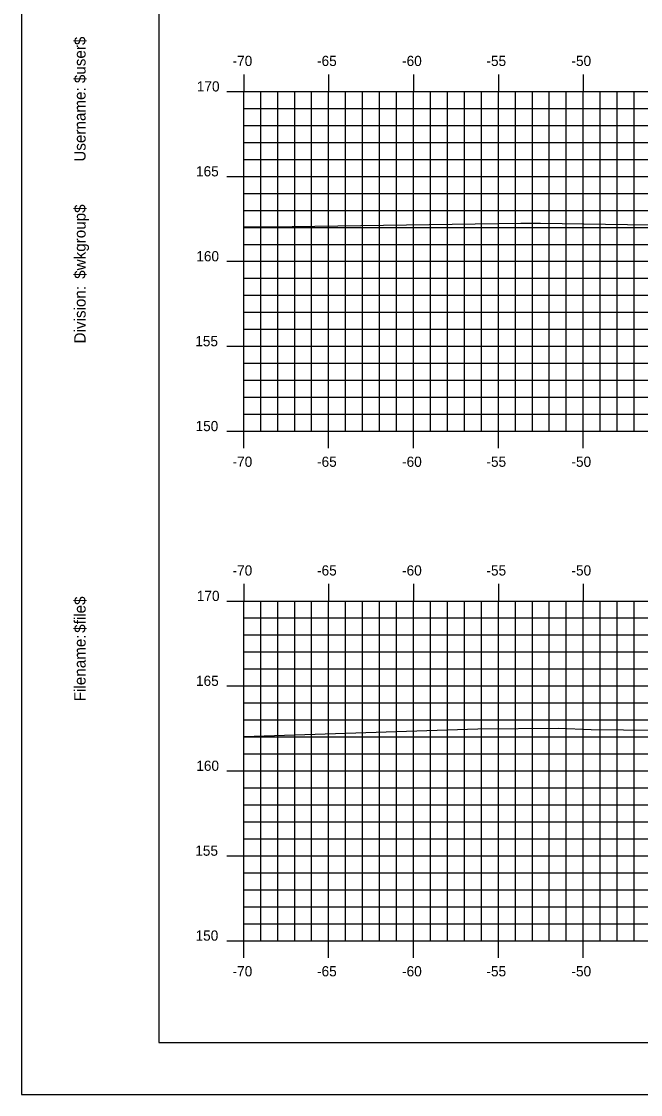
# Model space of a CAD drawing. Extents: x 1143198 to 1143368, y 608981 to 609091.
# Drawn here: x 1143198.2 to 1143234.7, y 608981.3 to 609044.5 of the extents above; entities that cross this region are included whole.
import ezdxf

# ---------------------------------------------------------------- set-up
doc = ezdxf.new("R2010")
doc.units = 0
for name, color, linetype in [('BORDER', 7, 'Continuous'), ('H_V ANNOTATION', 7, 'Continuous'), ('MAJOR', 7, 'Continuous'), ('MINOR', 7, 'Continuous'), ('PLOT BOUNDARY', 7, 'Continuous'), ('S_Roadway_Centerline', 7, 'Continuous')]:
    doc.layers.add(name, color=color, linetype=linetype)

msp = doc.modelspace()

# ---------------------------------------------------------------- linework, layer by layer
at = {"layer": 'BORDER'}
msp.add_lwpolyline([(1143206.323, 608984.335), (1143366.323, 608984.335), (1143366.323, 609089.335), (1143206.323, 609089.335)], close=True, dxfattribs=at)
at = {"layer": 'MAJOR'}
for p, q in [((1143211.323, 609041.337), (1143211.323, 609040.335)), ((1143216.323, 609041.337), (1143216.323, 609040.335)), ((1143221.323, 609041.337), (1143221.323, 609040.335)), ((1143226.323, 609041.337), (1143226.323, 609040.335)), ((1143231.323, 609041.337), (1143231.323, 609040.335)), ((1143210.321, 609040.335), (1143211.323, 609040.335)), ((1143211.323, 609040.335), (1143351.323, 609040.335)), ((1143211.323, 609020.335), (1143211.323, 609040.335)), ((1143211.323, 609020.335), (1143211.323, 609040.335)), ((1143211.323, 609040.335), (1143351.323, 609040.335)), ((1143216.323, 609020.335), (1143216.323, 609040.335)), ((1143221.323, 609020.335), (1143221.323, 609040.335)), ((1143226.323, 609020.335), (1143226.323, 609040.335)), ((1143231.323, 609020.335), (1143231.323, 609040.335)), ((1143210.321, 609035.335), (1143211.323, 609035.335)), ((1143211.323, 609035.335), (1143351.323, 609035.335)), ((1143210.321, 609030.335), (1143211.323, 609030.335)), ((1143211.323, 609030.335), (1143351.323, 609030.335)), ((1143210.321, 609025.335), (1143211.323, 609025.335)), ((1143211.323, 609025.335), (1143351.323, 609025.335)), ((1143210.321, 609020.335), (1143211.323, 609020.335)), ((1143211.323, 609020.335), (1143351.323, 609020.335)), ((1143211.323, 609020.335), (1143351.323, 609020.335)), ((1143211.323, 609019.333), (1143211.323, 609020.335)), ((1143216.323, 609019.333), (1143216.323, 609020.335)), ((1143221.323, 609019.333), (1143221.323, 609020.335)), ((1143226.323, 609019.333), (1143226.323, 609020.335)), ((1143231.323, 609019.333), (1143231.323, 609020.335)), ((1143211.323, 609011.337), (1143211.323, 609010.335)), ((1143216.323, 609011.337), (1143216.323, 609010.335)), ((1143221.323, 609011.337), (1143221.323, 609010.335)), ((1143226.323, 609011.337), (1143226.323, 609010.335)), ((1143231.323, 609011.337), (1143231.323, 609010.335)), ((1143210.321, 609010.335), (1143211.323, 609010.335)), ((1143211.323, 609010.335), (1143351.323, 609010.335)), ((1143211.323, 608990.335), (1143211.323, 609010.335)), ((1143211.323, 608990.335), (1143211.323, 609010.335)), ((1143211.323, 609010.335), (1143351.323, 609010.335)), ((1143216.323, 608990.335), (1143216.323, 609010.335)), ((1143221.323, 608990.335), (1143221.323, 609010.335)), ((1143226.323, 608990.335), (1143226.323, 609010.335)), ((1143231.323, 608990.335), (1143231.323, 609010.335)), ((1143210.321, 609005.335), (1143211.323, 609005.335)), ((1143211.323, 609005.335), (1143351.323, 609005.335)), ((1143210.321, 609000.335), (1143211.323, 609000.335)), ((1143211.323, 609000.335), (1143351.323, 609000.335)), ((1143210.321, 608995.335), (1143211.323, 608995.335)), ((1143211.323, 608995.335), (1143351.323, 608995.335)), ((1143210.321, 608990.335), (1143211.323, 608990.335)), ((1143211.323, 608990.335), (1143351.323, 608990.335)), ((1143211.323, 608990.335), (1143351.323, 608990.335)), ((1143211.323, 608989.333), (1143211.323, 608990.335)), ((1143216.323, 608989.333), (1143216.323, 608990.335)), ((1143221.323, 608989.333), (1143221.323, 608990.335)), ((1143226.323, 608989.333), (1143226.323, 608990.335)), ((1143231.323, 608989.333), (1143231.323, 608990.335))]:
    msp.add_line(p, q, dxfattribs=at)
at = {"layer": 'MINOR'}
for p, q in [((1143212.323, 609020.335), (1143212.323, 609040.335)), ((1143213.323, 609020.335), (1143213.323, 609040.335)), ((1143214.323, 609020.335), (1143214.323, 609040.335)), ((1143215.323, 609020.335), (1143215.323, 609040.335)), ((1143217.323, 609020.335), (1143217.323, 609040.335)), ((1143218.323, 609020.335), (1143218.323, 609040.335)), ((1143219.323, 609020.335), (1143219.323, 609040.335)), ((1143220.323, 609020.335), (1143220.323, 609040.335)), ((1143222.323, 609020.335), (1143222.323, 609040.335)), ((1143223.323, 609020.335), (1143223.323, 609040.335)), ((1143224.323, 609020.335), (1143224.323, 609040.335)), ((1143225.323, 609020.335), (1143225.323, 609040.335)), ((1143227.323, 609020.335), (1143227.323, 609040.335)), ((1143228.323, 609020.335), (1143228.323, 609040.335)), ((1143229.323, 609020.335), (1143229.323, 609040.335)), ((1143230.323, 609020.335), (1143230.323, 609040.335)), ((1143232.323, 609020.335), (1143232.323, 609040.335)), ((1143233.323, 609020.335), (1143233.323, 609040.335)), ((1143234.323, 609020.335), (1143234.323, 609040.335)), ((1143211.323, 609039.335), (1143351.323, 609039.335)), ((1143211.323, 609039.335), (1143212.325, 609039.335)), ((1143211.323, 609038.335), (1143351.323, 609038.335)), ((1143211.323, 609038.335), (1143212.325, 609038.335)), ((1143211.323, 609037.335), (1143351.323, 609037.335)), ((1143211.323, 609037.335), (1143212.325, 609037.335)), ((1143211.323, 609036.335), (1143351.323, 609036.335)), ((1143211.323, 609036.335), (1143212.325, 609036.335)), ((1143211.323, 609034.335), (1143351.323, 609034.335)), ((1143211.323, 609034.335), (1143212.325, 609034.335)), ((1143211.323, 609033.335), (1143351.323, 609033.335)), ((1143211.323, 609033.335), (1143212.325, 609033.335)), ((1143211.323, 609032.335), (1143351.323, 609032.335)), ((1143211.323, 609032.335), (1143212.325, 609032.335)), ((1143211.323, 609031.335), (1143351.323, 609031.335)), ((1143211.323, 609031.335), (1143212.325, 609031.335)), ((1143211.323, 609029.335), (1143351.323, 609029.335)), ((1143211.323, 609029.335), (1143212.325, 609029.335)), ((1143211.323, 609028.335), (1143351.323, 609028.335)), ((1143211.323, 609028.335), (1143212.325, 609028.335)), ((1143211.323, 609027.335), (1143351.323, 609027.335)), ((1143211.323, 609027.335), (1143212.325, 609027.335)), ((1143211.323, 609026.335), (1143351.323, 609026.335)), ((1143211.323, 609026.335), (1143212.325, 609026.335)), ((1143211.323, 609024.335), (1143351.323, 609024.335)), ((1143211.323, 609024.335), (1143212.325, 609024.335)), ((1143211.323, 609023.335), (1143351.323, 609023.335)), ((1143211.323, 609023.335), (1143212.325, 609023.335)), ((1143211.323, 609022.335), (1143351.323, 609022.335)), ((1143211.323, 609022.335), (1143212.325, 609022.335)), ((1143211.323, 609021.335), (1143351.323, 609021.335)), ((1143211.323, 609021.335), (1143212.325, 609021.335)), ((1143212.323, 608990.335), (1143212.323, 609010.335)), ((1143213.323, 608990.335), (1143213.323, 609010.335)), ((1143214.323, 608990.335), (1143214.323, 609010.335)), ((1143215.323, 608990.335), (1143215.323, 609010.335)), ((1143217.323, 608990.335), (1143217.323, 609010.335)), ((1143218.323, 608990.335), (1143218.323, 609010.335)), ((1143219.323, 608990.335), (1143219.323, 609010.335)), ((1143220.323, 608990.335), (1143220.323, 609010.335)), ((1143222.323, 608990.335), (1143222.323, 609010.335)), ((1143223.323, 608990.335), (1143223.323, 609010.335)), ((1143224.323, 608990.335), (1143224.323, 609010.335)), ((1143225.323, 608990.335), (1143225.323, 609010.335)), ((1143227.323, 608990.335), (1143227.323, 609010.335)), ((1143228.323, 608990.335), (1143228.323, 609010.335)), ((1143229.323, 608990.335), (1143229.323, 609010.335)), ((1143230.323, 608990.335), (1143230.323, 609010.335)), ((1143232.323, 608990.335), (1143232.323, 609010.335)), ((1143233.323, 608990.335), (1143233.323, 609010.335)), ((1143234.323, 608990.335), (1143234.323, 609010.335)), ((1143211.323, 609009.335), (1143351.323, 609009.335)), ((1143211.323, 609009.335), (1143212.325, 609009.335)), ((1143211.323, 609008.335), (1143351.323, 609008.335)), ((1143211.323, 609008.335), (1143212.325, 609008.335)), ((1143211.323, 609007.335), (1143351.323, 609007.335)), ((1143211.323, 609007.335), (1143212.325, 609007.335)), ((1143211.323, 609006.335), (1143351.323, 609006.335)), ((1143211.323, 609006.335), (1143212.325, 609006.335)), ((1143211.323, 609004.335), (1143351.323, 609004.335)), ((1143211.323, 609004.335), (1143212.325, 609004.335)), ((1143211.323, 609003.335), (1143351.323, 609003.335)), ((1143211.323, 609003.335), (1143212.325, 609003.335)), ((1143211.323, 609002.335), (1143351.323, 609002.335)), ((1143211.323, 609002.335), (1143212.325, 609002.335)), ((1143211.323, 609001.335), (1143351.323, 609001.335)), ((1143211.323, 609001.335), (1143212.325, 609001.335)), ((1143211.323, 608999.335), (1143351.323, 608999.335)), ((1143211.323, 608999.335), (1143212.325, 608999.335)), ((1143211.323, 608998.335), (1143351.323, 608998.335)), ((1143211.323, 608998.335), (1143212.325, 608998.335)), ((1143211.323, 608997.335), (1143351.323, 608997.335)), ((1143211.323, 608997.335), (1143212.325, 608997.335)), ((1143211.323, 608996.335), (1143351.323, 608996.335)), ((1143211.323, 608996.335), (1143212.325, 608996.335)), ((1143211.323, 608994.335), (1143351.323, 608994.335)), ((1143211.323, 608994.335), (1143212.325, 608994.335)), ((1143211.323, 608993.335), (1143351.323, 608993.335)), ((1143211.323, 608993.335), (1143212.325, 608993.335)), ((1143211.323, 608992.335), (1143351.323, 608992.335)), ((1143211.323, 608992.335), (1143212.325, 608992.335)), ((1143211.323, 608991.335), (1143351.323, 608991.335)), ((1143211.323, 608991.335), (1143212.325, 608991.335))]:
    msp.add_line(p, q, dxfattribs=at)
at = {"layer": 'PLOT BOUNDARY'}
msp.add_lwpolyline([(1143198.23, 608981.276), (1143368.23, 608981.276), (1143368.23, 609091.276), (1143198.23, 609091.276)], close=True, dxfattribs=at)
at = {"layer": 'S_Roadway_Centerline'}
for points in [[(1143211.323, 609032.36), (1143212.821, 609032.367), (1143227.649, 609032.583), (1143228.657, 609032.591), (1143228.8, 609032.583), (1143247.983, 609032.292), (1143251.333, 609031.712), (1143252.666, 609031.463), (1143252.702, 609031.479), (1143255.498, 609032.264), (1143255.639, 609032.274), (1143258.901, 609032.437), (1143269.916, 609032.935), (1143270.397, 609032.96), (1143280.959, 609032.894), (1143281.429, 609032.891), (1143281.615, 609032.872), (1143286.632, 609032.483), (1143289.312, 609031.85), (1143289.514, 609031.79), (1143294.73, 609032.394), (1143294.969, 609032.411), (1143322.054, 609032.585)], [(1143211.323, 609002.363), (1143225.121, 609002.802), (1143229.877, 609002.851), (1143231.792, 609002.771), (1143250.788, 609002.578), (1143255.519, 609001.533), (1143255.814, 609001.5), (1143256.006, 609001.549), (1143258.121, 609002.489), (1143262.156, 609002.773), (1143262.353, 609002.794), (1143272.425, 609003.307), (1143273.453, 609003.347), (1143283.253, 609003.281), (1143284.582, 609003.27), (1143284.986, 609003.233), (1143288.677, 609002.857), (1143291.938, 609001.891), (1143292.456, 609001.78), (1143295.537, 609001.911), (1143298.268, 609002.095)]]:
    msp.add_lwpolyline(points, dxfattribs=at)

# ---------------------------------------------------------------- texts
at = {"layer": 'BORDER'}
for s, p in [('$user$', (1143202.008, 609040.827)), ('Username:', (1143202.008, 609036.203)), ('$wkgroup$', (1143202.008, 609029.305)), ('Division:', (1143202.008, 609025.501)), ('$file$', (1143202.008, 609008.461)), ('Filename:', (1143202.008, 609004.433))]:
    msp.add_text(s, height=0.6696, rotation=90, dxfattribs=at).set_placement(p)
at = {"layer": 'H_V ANNOTATION'}
for s, p in [('-70', (1143210.665, 609041.835)), ('-65', (1143215.641, 609041.835)), ('-60', (1143220.649, 609041.835)), ('-55', (1143225.619, 609041.835)), ('-50', (1143230.627, 609041.835)), ('170', (1143208.56, 609040.335)), ('165', (1143208.512, 609035.335)), ('160', (1143208.528, 609030.335)), ('155', (1143208.469, 609025.335)), ('150', (1143208.485, 609020.335)), ('-70', (1143210.665, 609018.235)), ('-65', (1143215.641, 609018.235)), ('-60', (1143220.649, 609018.235)), ('-55', (1143225.619, 609018.235)), ('-50', (1143230.627, 609018.235)), ('-70', (1143210.665, 609011.835)), ('-65', (1143215.641, 609011.835)), ('-60', (1143220.649, 609011.835)), ('-55', (1143225.619, 609011.835)), ('-50', (1143230.627, 609011.835)), ('170', (1143208.56, 609010.335)), ('165', (1143208.512, 609005.335)), ('160', (1143208.528, 609000.335)), ('155', (1143208.469, 608995.335)), ('150', (1143208.485, 608990.335)), ('-70', (1143210.665, 608988.235)), ('-65', (1143215.641, 608988.235)), ('-60', (1143220.649, 608988.235)), ('-55', (1143225.619, 608988.235)), ('-50', (1143230.627, 608988.235))]:
    msp.add_text(s, height=0.6, dxfattribs=at).set_placement(p)
at = {"layer": 'MAJOR'}
for p in [(1143211.319, 609020.335), (1143211.319, 608990.335)]:
    msp.add_text('-', height=0.006, dxfattribs=at).set_placement(p)

doc.saveas('drawing.dxf')
